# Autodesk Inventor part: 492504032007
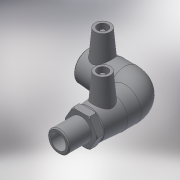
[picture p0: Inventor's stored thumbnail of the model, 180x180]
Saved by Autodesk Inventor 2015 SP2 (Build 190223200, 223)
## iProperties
Created: 2017-06
Part Number: 492504032007
Material: Generic
Description: PLASSON 90° ELBOW MALE TRANSITION 32-3/4"
Document SubType Name: Modeling
Designer: KIM
Mass: 115.687 g
Surface Area: 366.515 cm^2
Volume: 115.687 cm^3
Density: 1 g/cm^3
Appearance: Default
Author: KIM
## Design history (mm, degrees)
derived "492504.ipt"
feature "Solid1::492504.ipt"
tag "TaggingFeature1"
body "Solid1"
other parameters: "d2" = 44, "d4" = 27.66667, "d5" = 39.6, "d8" = 168 deg, "d10" = 16, "d11" = 5.33333, "d29" = 43, "d30" = 15, "d31" = 45.65, "d34" = 5 deg, "d41" = 4, "d42" = 14, "d43" = 0, "d48" = 61, "d49" = 32, "d50" = 27.2, "d51" = 16, "d54" = 90 deg, "d57" = 32, "d59" = 0, "d61" = 90 deg, "d86" = 3, "d87" = 0, "d93" = 0.1, "d94" = 7.25, "d95" = 26.441, "d96" = 18.5087, "d97" = 23, "d98" = 29, "d99" = 44, "d100" = 26.1, "d102" = 1.6, "d106" = 0, "d_" = 32, "L_" = 112, "D_" = 23, "A_" = 43, "d_2" = 12, "L_2" = 29, "D_1" = 44, "R_" = 26.441
